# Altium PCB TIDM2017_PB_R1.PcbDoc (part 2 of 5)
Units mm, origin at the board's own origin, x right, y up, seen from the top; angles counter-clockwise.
Board outline 120 x 147.5 mm, 4 copper layers (Top Layer, L2, L3, Bottom Layer), stack 1.413 mm thick; 117 components, 53 nets, 3137 pads, 96 vias.
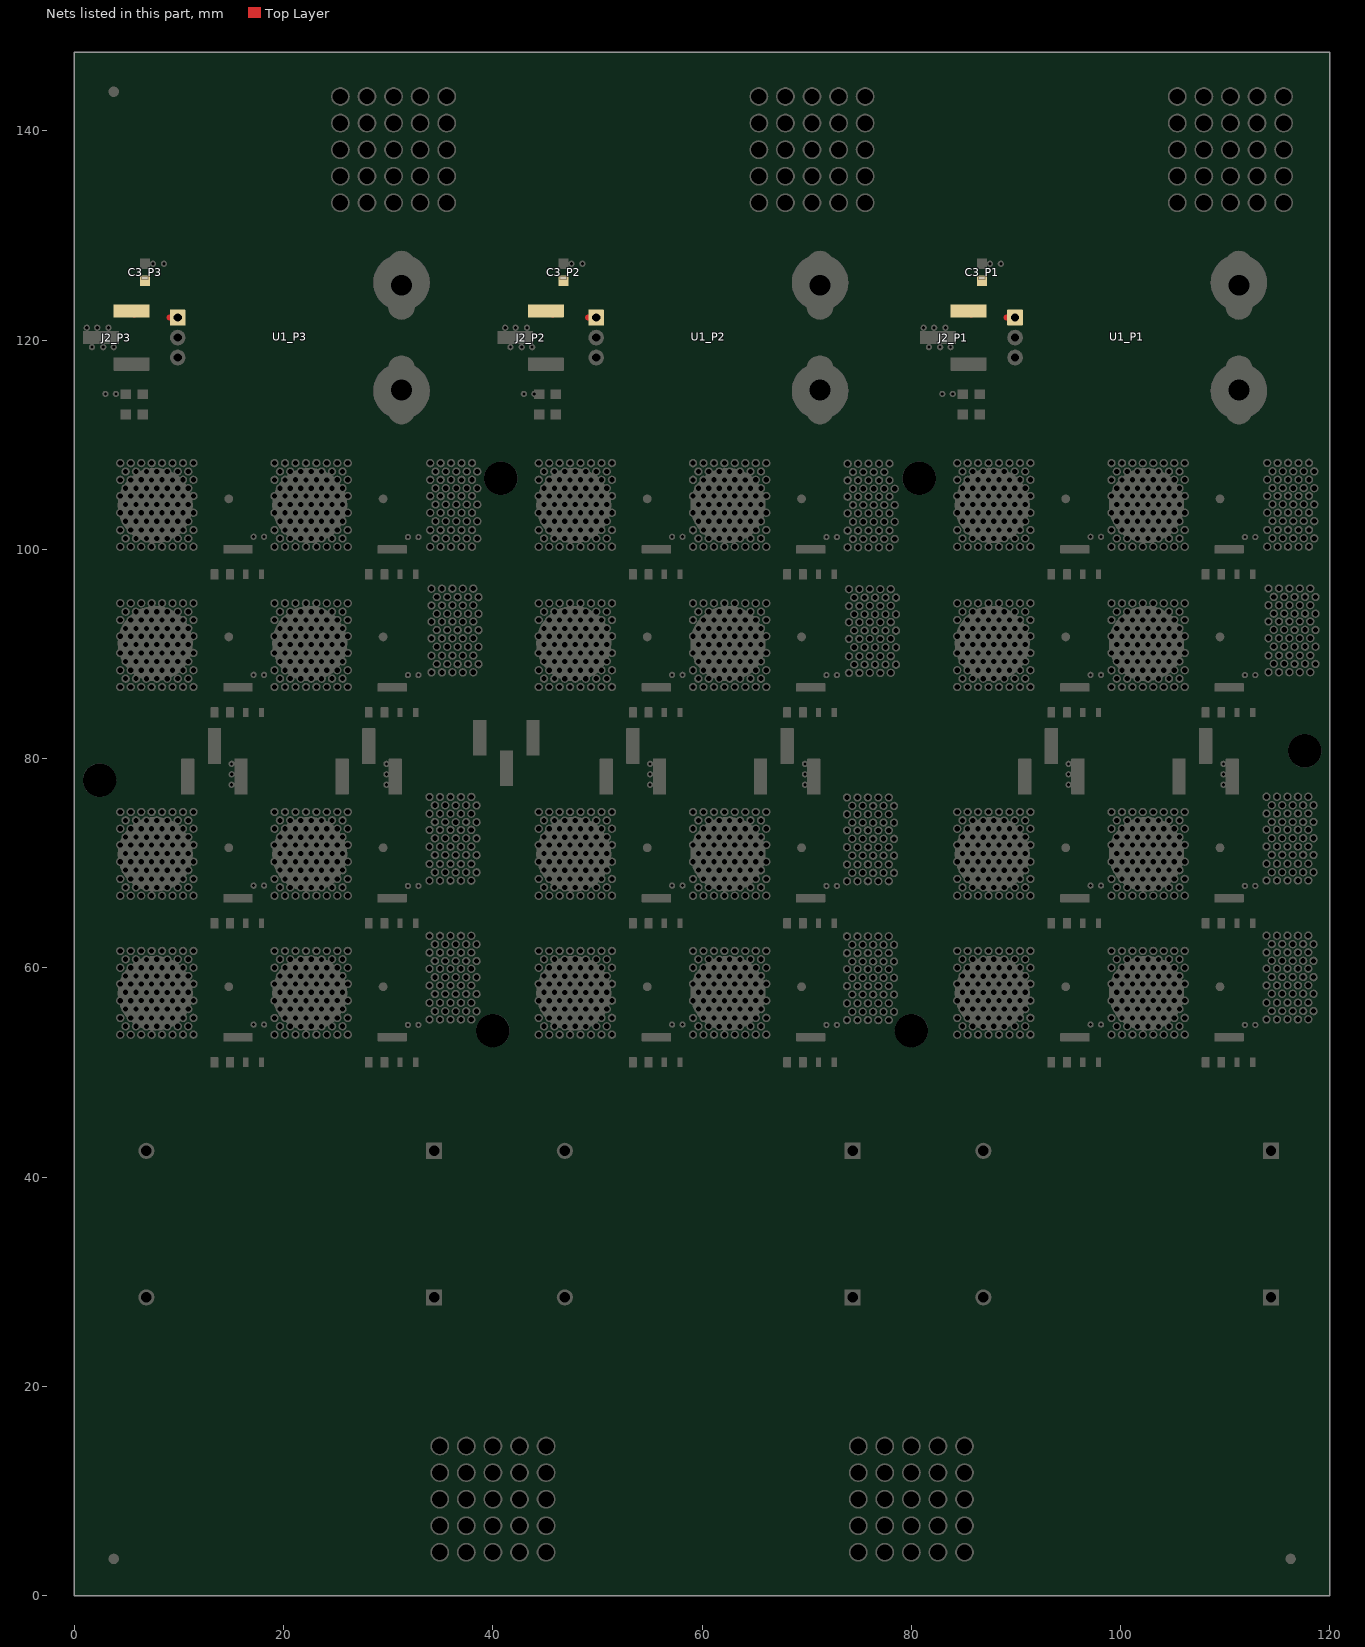
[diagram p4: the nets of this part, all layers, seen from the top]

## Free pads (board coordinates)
  round 0.6 hole 0.3: 2(1.175,121.183) 2(1.675,119.33) 2(2.175,121.186) 2(2.75,119.33) 2(2.955,114.858) 2(3.25,121.186) 2(3.75,119.33) 2(3.955,114.858) 2(7.5,127.3) 2(8.55,127.3) 2(15.026,77.5) 2(15.026,79.5) 2(15.029,78.5) 2(17.126,54.572) 2(17.126,67.855) 2(17.126,88.008) 2(17.126,101.203) 2(18.126,54.572) 2(18.126,67.855) 2(18.126,88.008) 2(18.126,101.203) 2(29.826,77.5) 2(29.826,78.5) 2(29.826,79.5) 2(31.876,54.547) 2(31.876,67.83) 2(31.876,87.983) 2(31.876,101.178) 2(32.876,54.547) 2(32.876,67.83) 2(32.876,87.983) 2(32.876,101.178) 2(41.175,121.183) 2(41.675,119.33) 2(42.175,121.186) 2(42.75,119.33) 2(42.955,114.858) 2(43.25,121.186) 2(43.75,119.33) 2(43.955,114.858) 2(47.5,127.3) 2(48.55,127.3) 2(55.026,77.5) 2(55.026,79.5) 2(55.029,78.5) 2(57.126,54.572) 2(57.126,67.855) 2(57.126,88.008) 2(57.126,101.203) 2(58.126,54.572) 2(58.126,67.855) 2(58.126,88.008) 2(58.126,101.203) 2(69.826,77.5) 2(69.826,78.5) 2(69.826,79.5) 2(71.876,54.547) 2(71.876,67.83) 2(71.876,87.983) 2(71.876,101.178) 2(72.876,54.547) 2(72.876,67.83) 2(72.876,87.983) 2(72.876,101.178) 2(81.175,121.183) 2(81.675,119.33) 2(82.175,121.186) 2(82.75,119.33) 2(82.955,114.858) 2(83.25,121.186) 2(83.75,119.33) 2(83.955,114.858) 2(87.5,127.3) 2(88.55,127.3) 2(95.026,77.5) 2(95.026,79.5) 2(95.029,78.5) 2(97.126,54.572) 2(97.126,67.855) 2(97.126,88.008) 2(97.126,101.203) 2(98.126,54.572) 2(98.126,67.855) 2(98.126,88.008) 2(98.126,101.203) 2(109.826,77.5) 2(109.826,78.5) 2(109.826,79.5) 2(111.876,54.547) 2(111.876,67.83) 2(111.876,87.983) 2(111.876,101.178) 2(112.876,54.547) 2(112.876,67.83) 2(112.876,87.983) 2(112.876,101.178)
  round 0.8 hole 0.5: 2(4.376,53.611) 2(4.376,55.211) 2(4.376,56.861) 2(4.376,58.461) 2(4.376,60.014) 2(4.376,61.614) 2(4.376,66.894) 2(4.376,68.494) 2(4.376,70.144) 2(4.376,71.744) 2(4.376,73.297) 2(4.376,74.897) 2(4.376,86.847) 2(4.376,88.447) 2(4.376,90.097) 2(4.376,91.697) 2(4.376,93.25) 2(4.376,94.85) 2(4.376,100.242) 2(4.376,101.842) 2(4.376,103.492) 2(4.376,105.092) 2(4.376,106.644) 2(4.376,108.244) 2(4.889,54.409) 2(4.889,56.059) 2(4.889,57.659) 2(4.889,59.212) 2(4.889,60.812) 2(4.889,67.693) 2(4.889,69.343) 2(4.889,70.943) 2(4.889,72.496) 2(4.889,74.096) 2(4.889,87.646) 2(4.889,89.296) 2(4.889,90.896) 2(4.889,92.448) 2(4.889,94.048) 2(4.889,101.04) 2(4.889,102.69) 2(4.889,104.29) 2(4.889,105.843) 2(4.889,107.443) 2(5.376,53.611) 2(5.376,55.211) 2(5.376,56.861) 2(5.376,58.461) 2(5.376,60.014) 2(5.376,61.614) 2(5.376,66.894) 2(5.376,68.494) 2(5.376,70.144) 2(5.376,71.744) 2(5.376,73.297) 2(5.376,74.897) 2(5.376,86.847) 2(5.376,88.447) 2(5.376,90.097) 2(5.376,91.697) 2(5.376,93.25) 2(5.376,94.85) 2(5.376,100.242) 2(5.376,101.842) 2(5.376,103.492) 2(5.376,105.092) 2(5.376,106.644) 2(5.376,108.244) 2(5.876,54.409) 2(5.876,56.059) 2(5.876,57.659) 2(5.876,59.212) 2(5.876,60.812) 2(5.876,67.693) 2(5.876,69.343) 2(5.876,70.943) 2(5.876,72.496) 2(5.876,74.096) 2(5.876,87.646) 2(5.876,89.296) 2(5.876,90.896) 2(5.876,92.448) 2(5.876,94.048) 2(5.876,101.04) 2(5.876,102.69) 2(5.876,104.29) 2(5.876,105.843) 2(5.876,107.443) 2(6.376,53.616) 2(6.376,55.216) 2(6.376,56.866) 2(6.376,58.466) 2(6.376,60.019) 2(6.376,61.619) 2(6.376,66.9) 2(6.376,68.5) 2(6.376,70.15) 2(6.376,71.75) 2(6.376,73.303) 2(6.376,74.903) 2(6.376,86.853) 2(6.376,88.453) 2(6.376,90.103) 2(6.376,91.703) 2(6.376,93.256) 2(6.376,94.855) 2(6.376,100.247) 2(6.376,101.847) 2(6.376,103.497) 2(6.376,105.097) 2(6.376,106.65) 2(6.376,108.25) 2(6.876,54.404) 2(6.876,56.054) 2(6.876,57.654) 2(6.876,59.207) 2(6.876,60.807) 2(6.876,67.687) 2(6.876,69.337) 2(6.876,70.937) 2(6.876,72.49) 2(6.876,74.09) 2(6.876,87.64) 2(6.876,89.29) 2(6.876,90.89) 2(6.876,92.443) 2(6.876,94.043) 2(6.876,101.035) 2(6.876,102.685) 2(6.876,104.285) 2(6.876,105.837) 2(6.876,107.437) 2(7.376,53.611) 2(7.376,55.211) 2(7.376,56.861) 2(7.376,58.461) 2(7.376,60.014) 2(7.376,61.614) 2(7.376,66.894) 2(7.376,68.494) 2(7.376,70.144) 2(7.376,71.744) 2(7.376,73.297) 2(7.376,74.897) 2(7.376,86.847) 2(7.376,88.447) 2(7.376,90.097) 2(7.376,91.697) 2(7.376,93.25) 2(7.376,94.85) 2(7.376,100.242) 2(7.376,101.842) 2(7.376,103.492) 2(7.376,105.092) 2(7.376,106.644) 2(7.376,108.244) 2(7.876,54.409) 2(7.876,56.059) 2(7.876,57.659) 2(7.876,59.212) 2(7.876,60.812) 2(7.876,67.693) 2(7.876,69.343) 2(7.876,70.943) 2(7.876,72.496) 2(7.876,74.096) 2(7.876,87.646) 2(7.876,89.296) 2(7.876,90.896) 2(7.876,92.448) 2(7.876,94.048) 2(7.876,101.04) 2(7.876,102.69) 2(7.876,104.29) 2(7.876,105.843) 2(7.876,107.443) 2(8.376,53.616) 2(8.376,55.216) 2(8.376,56.866) 2(8.376,58.466) 2(8.376,60.019) 2(8.376,61.619) 2(8.376,66.9) 2(8.376,68.5) 2(8.376,70.15) 2(8.376,71.75) 2(8.376,73.303) 2(8.376,74.903) 2(8.376,86.853) 2(8.376,88.453) 2(8.376,90.103) 2(8.376,91.703) 2(8.376,93.256) 2(8.376,94.855) 2(8.376,100.247) 2(8.376,101.847) 2(8.376,103.497) 2(8.376,105.097) 2(8.376,106.65) 2(8.376,108.25) 2(8.876,54.404) 2(8.876,56.054) 2(8.876,57.654) 2(8.876,59.207) 2(8.876,60.807) 2(8.876,67.687) 2(8.876,69.337) 2(8.876,70.937) 2(8.876,72.49) 2(8.876,74.09) 2(8.876,87.64) 2(8.876,89.29) 2(8.876,90.89) 2(8.876,92.443) 2(8.876,94.043) 2(8.876,101.035) 2(8.876,102.685) 2(8.876,104.285) 2(8.876,105.837) 2(8.876,107.437) 2(9.376,53.611) 2(9.376,55.211) 2(9.376,56.861) 2(9.376,58.461) 2(9.376,60.014) 2(9.376,61.614) 2(9.376,66.894) 2(9.376,68.494) 2(9.376,70.144) 2(9.376,71.744) 2(9.376,73.297) 2(9.376,74.897) 2(9.376,86.847) 2(9.376,88.447) 2(9.376,90.097) 2(9.376,91.697) 2(9.376,93.25) 2(9.376,94.85) 2(9.376,100.242) 2(9.376,101.842) 2(9.376,103.492) 2(9.376,105.092) 2(9.376,106.644) 2(9.376,108.244) 2(9.876,54.409) 2(9.876,56.059) 2(9.876,57.659) 2(9.876,59.212) 2(9.876,60.812) 2(9.876,67.693) 2(9.876,69.343) 2(9.876,70.943) 2(9.876,72.496) 2(9.876,74.096) 2(9.876,87.646) 2(9.876,89.296) 2(9.876,90.896) 2(9.876,92.448) 2(9.876,94.048) 2(9.876,101.04) 2(9.876,102.69) 2(9.876,104.29) 2(9.876,105.843) 2(9.876,107.443) 2(10.376,53.616) 2(10.376,55.216) 2(10.376,56.866) 2(10.376,58.466) 2(10.376,60.019) 2(10.376,61.619) 2(10.376,66.9) 2(10.376,68.5) 2(10.376,70.15) 2(10.376,71.75) 2(10.376,73.303) 2(10.376,74.903) 2(10.376,86.853) 2(10.376,88.453) 2(10.376,90.103) 2(10.376,91.703) 2(10.376,93.256) 2(10.376,94.855) 2(10.376,100.247) 2(10.376,101.847) 2(10.376,103.497) 2(10.376,105.097) 2(10.376,106.65) 2(10.376,108.25) 2(10.876,54.409) 2(10.876,56.059) 2(10.876,57.659) 2(10.876,59.212) 2(10.876,60.812) 2(10.876,67.693) 2(10.876,69.343) 2(10.876,70.943) 2(10.876,72.496) 2(10.876,74.096) 2(10.876,87.646) 2(10.876,89.296) 2(10.876,90.896) 2(10.876,92.448) 2(10.876,94.048) 2(10.876,101.04) 2(10.876,102.69) 2(10.876,104.29) 2(10.876,105.843) 2(10.876,107.443) 2(11.376,53.616) 2(11.376,55.216) 2(11.376,56.866) 2(11.376,58.466) 2(11.376,60.019) 2(11.376,61.619) 2(11.376,66.9) 2(11.376,68.5) 2(11.376,70.15) 2(11.376,71.75) 2(11.376,73.303) 2(11.376,74.903) 2(11.376,86.853) 2(11.376,88.453) 2(11.376,90.103) 2(11.376,91.703) 2(11.376,93.256) 2(11.376,94.855) 2(11.376,100.247) 2(11.376,101.847) 2(11.376,103.497) 2(11.376,105.097) 2(11.376,106.65) 2(11.376,108.25) 2(19.126,53.611) 2(19.126,55.211) 2(19.126,56.861) 2(19.126,58.461) 2(19.126,60.014) 2(19.126,61.614) 2(19.126,66.894) 2(19.126,68.494) 2(19.126,70.144) 2(19.126,71.744) 2(19.126,73.297) 2(19.126,74.897) 2(19.126,86.847) 2(19.126,88.447) 2(19.126,90.097) 2(19.126,91.697) 2(19.126,93.25) 2(19.126,94.85) 2(19.126,100.242) 2(19.126,101.842) 2(19.126,103.492) 2(19.126,105.092) 2(19.126,106.644) 2(19.126,108.244) 2(19.639,54.409) 2(19.639,56.059) 2(19.639,57.659) 2(19.639,59.212) 2(19.639,60.812) 2(19.639,67.693) 2(19.639,69.343) 2(19.639,70.943) 2(19.639,72.496) 2(19.639,74.096) 2(19.639,87.646) 2(19.639,89.296) 2(19.639,90.896) 2(19.639,92.448) 2(19.639,94.048) 2(19.639,101.04) 2(19.639,102.69) 2(19.639,104.29) 2(19.639,105.843) 2(19.639,107.443) 2(20.126,53.611) 2(20.126,55.211) 2(20.126,56.861) 2(20.126,58.461) 2(20.126,60.014) 2(20.126,61.614) 2(20.126,66.894) 2(20.126,68.494) 2(20.126,70.144) 2(20.126,71.744) 2(20.126,73.297) 2(20.126,74.897) 2(20.126,86.847) 2(20.126,88.447) 2(20.126,90.097) 2(20.126,91.697) 2(20.126,93.25) 2(20.126,94.85) 2(20.126,100.242) 2(20.126,101.842) 2(20.126,103.492) 2(20.126,105.092) 2(20.126,106.644) 2(20.126,108.244) 2(20.626,54.409) 2(20.626,56.059) 2(20.626,57.659) 2(20.626,59.212) 2(20.626,60.812) 2(20.626,67.693) 2(20.626,69.343) 2(20.626,70.943) 2(20.626,72.496) 2(20.626,74.096) 2(20.626,87.646) 2(20.626,89.296) 2(20.626,90.896) 2(20.626,92.448) 2(20.626,94.048) 2(20.626,101.04) 2(20.626,102.69) 2(20.626,104.29) 2(20.626,105.843) 2(20.626,107.443) 2(21.126,53.616) 2(21.126,55.216) 2(21.126,56.866) 2(21.126,58.466) 2(21.126,60.019) 2(21.126,61.619) 2(21.126,66.9) 2(21.126,68.5) 2(21.126,70.15) 2(21.126,71.75) 2(21.126,73.303) 2(21.126,74.903) 2(21.126,86.853) 2(21.126,88.453) 2(21.126,90.103) 2(21.126,91.703) 2(21.126,93.256) 2(21.126,94.855) 2(21.126,100.247) 2(21.126,101.847) 2(21.126,103.497) 2(21.126,105.097) 2(21.126,106.65) 2(21.126,108.25) 2(21.626,54.404) 2(21.626,56.054) 2(21.626,57.654) 2(21.626,59.207) 2(21.626,60.807) 2(21.626,67.687) 2(21.626,69.337) 2(21.626,70.937) 2(21.626,72.49) 2(21.626,74.09) 2(21.626,87.64) 2(21.626,89.29) 2(21.626,90.89) 2(21.626,92.443) 2(21.626,94.043) 2(21.626,101.035) 2(21.626,102.685) 2(21.626,104.285) 2(21.626,105.837) 2(21.626,107.437) 2(22.126,53.611) 2(22.126,55.211) 2(22.126,56.861) 2(22.126,58.461) 2(22.126,60.014) 2(22.126,61.614) 2(22.126,66.894) 2(22.126,68.494) 2(22.126,70.144) 2(22.126,71.744) 2(22.126,73.297) 2(22.126,74.897) 2(22.126,86.847) 2(22.126,88.447) 2(22.126,90.097) 2(22.126,91.697) 2(22.126,93.25) 2(22.126,94.85) 2(22.126,100.242) 2(22.126,101.842) 2(22.126,103.492) 2(22.126,105.092) 2(22.126,106.644) 2(22.126,108.244) 2(22.626,54.409) 2(22.626,56.059) 2(22.626,57.659) 2(22.626,59.212) 2(22.626,60.812) 2(22.626,67.693) 2(22.626,69.343) 2(22.626,70.943) 2(22.626,72.496) 2(22.626,74.096) 2(22.626,87.646) 2(22.626,89.296) 2(22.626,90.896) 2(22.626,92.448) 2(22.626,94.048) 2(22.626,101.04) 2(22.626,102.69) 2(22.626,104.29) 2(22.626,105.843) 2(22.626,107.443) 2(23.126,53.616) 2(23.126,55.216) 2(23.126,56.866) 2(23.126,58.466) 2(23.126,60.019) 2(23.126,61.619) 2(23.126,66.9) 2(23.126,68.5) 2(23.126,70.15) 2(23.126,71.75) 2(23.126,73.303) 2(23.126,74.903) 2(23.126,86.853) 2(23.126,88.453) 2(23.126,90.103) 2(23.126,91.703) 2(23.126,93.256) 2(23.126,94.855) 2(23.126,100.247) 2(23.126,101.847) 2(23.126,103.497) 2(23.126,105.097) 2(23.126,106.65) 2(23.126,108.25) 2(23.626,54.404) 2(23.626,56.054) 2(23.626,57.654) 2(23.626,59.207) 2(23.626,60.807) 2(23.626,67.687) 2(23.626,69.337) 2(23.626,70.937) 2(23.626,72.49) 2(23.626,74.09) 2(23.626,87.64) 2(23.626,89.29) 2(23.626,90.89) 2(23.626,92.443) 2(23.626,94.043) 2(23.626,101.035) 2(23.626,102.685) 2(23.626,104.285) 2(23.626,105.837) 2(23.626,107.437) 2(24.126,53.611) 2(24.126,55.211) 2(24.126,56.861) 2(24.126,58.461) 2(24.126,60.014) 2(24.126,61.614) 2(24.126,66.894) 2(24.126,68.494) 2(24.126,70.144) 2(24.126,71.744) 2(24.126,73.297) 2(24.126,74.897) 2(24.126,86.847) 2(24.126,88.447) 2(24.126,90.097) 2(24.126,91.697) 2(24.126,93.25) 2(24.126,94.85) 2(24.126,100.242) 2(24.126,101.842) 2(24.126,103.492) 2(24.126,105.092) 2(24.126,106.644) 2(24.126,108.244) 2(24.626,54.409) 2(24.626,56.059) 2(24.626,57.659) 2(24.626,59.212) 2(24.626,60.812) 2(24.626,67.693) 2(24.626,69.343) 2(24.626,70.943) 2(24.626,72.496) 2(24.626,74.096) 2(24.626,87.646) 2(24.626,89.296) 2(24.626,90.896) 2(24.626,92.448) 2(24.626,94.048) 2(24.626,101.04) 2(24.626,102.69) 2(24.626,104.29) 2(24.626,105.843) 2(24.626,107.443) 2(25.126,53.616) 2(25.126,55.216) 2(25.126,56.866) 2(25.126,58.466) 2(25.126,60.019) 2(25.126,61.619) 2(25.126,66.9) 2(25.126,68.5) 2(25.126,70.15) 2(25.126,71.75) 2(25.126,73.303) 2(25.126,74.903) 2(25.126,86.853) 2(25.126,88.453) 2(25.126,90.103) 2(25.126,91.703) 2(25.126,93.256) 2(25.126,94.855) 2(25.126,100.247) 2(25.126,101.847) 2(25.126,103.497) 2(25.126,105.097) 2(25.126,106.65) 2(25.126,108.25) 2(25.626,54.409) 2(25.626,56.059) 2(25.626,57.659) 2(25.626,59.212) 2(25.626,60.812) 2(25.626,67.693) 2(25.626,69.343) 2(25.626,70.943) 2(25.626,72.496) 2(25.626,74.096) 2(25.626,87.646) 2(25.626,89.296) 2(25.626,90.896) 2(25.626,92.448) 2(25.626,94.048) 2(25.626,101.04) 2(25.626,102.69) 2(25.626,104.29) 2(25.626,105.843) 2(25.626,107.443) 2(26.126,53.616) 2(26.126,55.216) 2(26.126,56.866) 2(26.126,58.466) 2(26.126,60.019) 2(26.126,61.619) 2(26.126,66.9) 2(26.126,68.5) 2(26.126,70.15) 2(26.126,71.75) 2(26.126,73.303) 2(26.126,74.903) 2(26.126,86.853) 2(26.126,88.453) 2(26.126,90.103) 2(26.126,91.703) 2(26.126,93.256) 2(26.126,94.855) 2(26.126,100.247) 2(26.126,101.847) 2(26.126,103.497) 2(26.126,105.097) 2(26.126,106.65) 2(26.126,108.25) 2(33.939,55.054) 2(33.939,56.654) 2(33.939,58.304) 2(33.939,59.904) 2(33.939,61.457) 2(33.939,63.057) 2(33.939,68.332) 2(33.939,69.932) 2(33.939,71.582) 2(33.939,73.182) 2(33.939,74.735) 2(33.939,76.335) 2(34.001,100.242) 2(34.001,101.842) 2(34.001,103.492) 2(34.001,105.092) 2(34.001,106.644) 2(34.001,108.244) 2(34.126,88.242) 2(34.126,89.842) 2(34.126,91.492) 2(34.126,93.092) 2(34.126,94.644) 2(34.126,96.244) 2(34.452,55.852) 2(34.452,57.502) 2(34.452,59.102) 2(34.452,60.655) 2(34.452,62.255) 2(34.452,69.13) 2(34.452,70.78) 2(34.452,72.38) 2(34.452,73.933) 2(34.452,75.533) 2(34.514,101.04) 2(34.514,102.69) 2(34.514,104.29) 2(34.514,105.843) 2(34.514,107.443) 2(34.639,89.04) 2(34.639,90.69) 2(34.639,92.29) 2(34.639,93.843) 2(34.639,95.443) 2(34.939,55.054) 2(34.939,56.654) 2(34.939,58.304) 2(34.939,59.904) 2(34.939,61.457) 2(34.939,63.057) 2(34.939,68.332) 2(34.939,69.932) 2(34.939,71.582) 2(34.939,73.182) 2(34.939,74.735) 2(34.939,76.335) 2(35.001,100.242) 2(35.001,101.842) 2(35.001,103.492) 2(35.001,105.092) 2(35.001,106.644) 2(35.001,108.244) 2(35.126,88.242) 2(35.126,89.842) 2(35.126,91.492) 2(35.126,93.092) 2(35.126,94.644) 2(35.126,96.244) 2(35.439,55.852) 2(35.439,57.502) 2(35.439,59.102) 2(35.439,60.655) 2(35.439,62.255) 2(35.439,69.13) 2(35.439,70.78) 2(35.439,72.38) 2(35.439,73.933) 2(35.439,75.533) 2(35.501,101.04) 2(35.501,102.69) 2(35.501,104.29) 2(35.501,105.843) 2(35.501,107.443) 2(35.626,89.04) 2(35.626,90.69) 2(35.626,92.29) 2(35.626,93.843) 2(35.626,95.443) 2(35.939,55.059) 2(35.939,56.659) 2(35.939,58.309) 2(35.939,59.909) 2(35.939,61.462) 2(35.939,63.062) 2(35.939,68.337) 2(35.939,69.937) 2(35.939,71.587) 2(35.939,73.187) 2(35.939,74.74) 2(35.939,76.34) 2(36.001,100.247) 2(36.001,101.847) 2(36.001,103.497) 2(36.001,105.097) 2(36.001,106.65) 2(36.001,108.25) 2(36.126,88.247) 2(36.126,89.847) 2(36.126,91.497) 2(36.126,93.097) 2(36.126,94.65) 2(36.126,96.25) 2(36.439,55.847) 2(36.439,57.497) 2(36.439,59.097) 2(36.439,60.649) 2(36.439,62.249) 2(36.439,69.125) 2(36.439,70.775) 2(36.439,72.375) 2(36.439,73.927) 2(36.439,75.527) 2(36.501,101.035) 2(36.501,102.685) 2(36.501,104.285) 2(36.501,105.837) 2(36.501,107.437) 2(36.626,89.035) 2(36.626,90.685) 2(36.626,92.285) 2(36.626,93.837) 2(36.626,95.437) 2(36.939,55.054) 2(36.939,56.654) 2(36.939,58.304) 2(36.939,59.904) 2(36.939,61.457) 2(36.939,63.057) 2(36.939,68.332) 2(36.939,69.932) 2(36.939,71.582) 2(36.939,73.182) 2(36.939,74.735) 2(36.939,76.335) 2(37.001,100.242) 2(37.001,101.842) 2(37.001,103.492) 2(37.001,105.092) 2(37.001,106.644) 2(37.001,108.244) 2(37.126,88.242) 2(37.126,89.842) 2(37.126,91.492) 2(37.126,93.092) 2(37.126,94.644) 2(37.126,96.244) 2(37.439,55.852) 2(37.439,57.502) 2(37.439,59.102) 2(37.439,60.655) 2(37.439,62.255) 2(37.439,69.13) 2(37.439,70.78) 2(37.439,72.38) 2(37.439,73.933) 2(37.439,75.533) 2(37.501,101.04) 2(37.501,102.69) 2(37.501,104.29) 2(37.501,105.843) 2(37.501,107.443) 2(37.626,89.04) 2(37.626,90.69) 2(37.626,92.29) 2(37.626,93.843) 2(37.626,95.443) 2(37.939,55.059) 2(37.939,56.659) 2(37.939,58.309) 2(37.939,59.909) 2(37.939,61.462) 2(37.939,63.062) 2(37.939,68.337) 2(37.939,69.937) 2(37.939,71.587) 2(37.939,73.187) 2(37.939,74.74) 2(37.939,76.34) 2(38.001,100.247) 2(38.001,101.847) 2(38.001,103.497) 2(38.001,105.097) 2(38.001,106.65) 2(38.001,108.25) 2(38.126,88.247) 2(38.126,89.847) 2(38.126,91.497) 2(38.126,93.097) 2(38.126,94.65) 2(38.126,96.25) 2(38.439,55.847) 2(38.439,57.497) 2(38.439,59.097) 2(38.439,60.649) 2(38.439,62.249) 2(38.439,69.125) 2(38.439,70.775) 2(38.439,72.375) 2(38.439,73.927) 2(38.439,75.527) 2(38.501,101.035) 2(38.501,102.685) 2(38.501,104.285) 2(38.501,105.837) 2(38.501,107.437) 2(38.626,89.035) 2(38.626,90.685) 2(38.626,92.285) 2(38.626,93.837) 2(38.626,95.437) 2(44.376,53.611) 2(44.376,55.211) 2(44.376,56.861) 2(44.376,58.461) 2(44.376,60.014) 2(44.376,61.614) 2(44.376,66.894) 2(44.376,68.494) 2(44.376,70.144) 2(44.376,71.744) 2(44.376,73.297) 2(44.376,74.897) 2(44.376,86.847) 2(44.376,88.447) 2(44.376,90.097) 2(44.376,91.697) 2(44.376,93.25) 2(44.376,94.85) 2(44.376,100.242) 2(44.376,101.842) 2(44.376,103.492) 2(44.376,105.092) 2(44.376,106.644) 2(44.376,108.244) 2(44.889,54.409) 2(44.889,56.059) 2(44.889,57.659) 2(44.889,59.212) 2(44.889,60.812) 2(44.889,67.693) 2(44.889,69.343) 2(44.889,70.943) 2(44.889,72.496) 2(44.889,74.096) 2(44.889,87.646) 2(44.889,89.296) 2(44.889,90.896) 2(44.889,92.448) 2(44.889,94.048) 2(44.889,101.04) 2(44.889,102.69) 2(44.889,104.29) 2(44.889,105.843) 2(44.889,107.443) 2(45.376,53.611) 2(45.376,55.211) 2(45.376,56.861) 2(45.376,58.461) 2(45.376,60.014) 2(45.376,61.614) 2(45.376,66.894) 2(45.376,68.494) 2(45.376,70.144) 2(45.376,71.744) 2(45.376,73.297) 2(45.376,74.897) 2(45.376,86.847) 2(45.376,88.447) 2(45.376,90.097) 2(45.376,91.697) 2(45.376,93.25) 2(45.376,94.85) 2(45.376,100.242) 2(45.376,101.842) 2(45.376,103.492) 2(45.376,105.092) 2(45.376,106.644) 2(45.376,108.244) 2(45.876,54.409) 2(45.876,56.059) 2(45.876,57.659) 2(45.876,59.212) 2(45.876,60.812) 2(45.876,67.693) 2(45.876,69.343) 2(45.876,70.943) 2(45.876,72.496) 2(45.876,74.096) 2(45.876,87.646) 2(45.876,89.296) 2(45.876,90.896) 2(45.876,92.448) 2(45.876,94.048) 2(45.876,101.04) 2(45.876,102.69) 2(45.876,104.29) 2(45.876,105.843) 2(45.876,107.443) 2(46.376,53.616) 2(46.376,55.216) 2(46.376,56.866) 2(46.376,58.466) 2(46.376,60.019) 2(46.376,61.619) 2(46.376,66.9) 2(46.376,68.5) 2(46.376,70.15) 2(46.376,71.75) 2(46.376,73.303) 2(46.376,74.903) 2(46.376,86.853) 2(46.376,88.453) 2(46.376,90.103) 2(46.376,91.703) 2(46.376,93.256) 2(46.376,94.855) 2(46.376,100.247) 2(46.376,101.847) 2(46.376,103.497) 2(46.376,105.097) 2(46.376,106.65) 2(46.376,108.25) 2(46.876,54.404) 2(46.876,56.054) 2(46.876,57.654) 2(46.876,59.207) 2(46.876,60.807) 2(46.876,67.687) 2(46.876,69.337) 2(46.876,70.937) 2(46.876,72.49) 2(46.876,74.09) 2(46.876,87.64) 2(46.876,89.29) 2(46.876,90.89) 2(46.876,92.443) 2(46.876,94.043) 2(46.876,101.035) 2(46.876,102.685) 2(46.876,104.285) 2(46.876,105.837) 2(46.876,107.437) 2(47.376,53.611) 2(47.376,55.211) 2(47.376,56.861) 2(47.376,58.461) 2(47.376,60.014) 2(47.376,61.614) 2(47.376,66.894) 2(47.376,68.494) 2(47.376,70.144) 2(47.376,71.744) 2(47.376,73.297) 2(47.376,74.897) 2(47.376,86.847) 2(47.376,88.447) 2(47.376,90.097) 2(47.376,91.697) 2(47.376,93.25) 2(47.376,94.85) 2(47.376,100.242) 2(47.376,101.842) 2(47.376,103.492) 2(47.376,105.092) 2(47.376,106.644) 2(47.376,108.244) 2(47.876,54.409) 2(47.876,56.059) 2(47.876,57.659) 2(47.876,59.212) 2(47.876,60.812) 2(47.876,67.693) 2(47.876,69.343) 2(47.876,70.943) 2(47.876,72.496) 2(47.876,74.096) 2(47.876,87.646) 2(47.876,89.296) 2(47.876,90.896) 2(47.876,92.448) 2(47.876,94.048) 2(47.876,101.04) 2(47.876,102.69) 2(47.876,104.29) 2(47.876,105.843) 2(47.876,107.443) 2(48.376,53.616) 2(48.376,55.216) 2(48.376,56.866) 2(48.376,58.466) 2(48.376,60.019) 2(48.376,61.619) 2(48.376,66.9) 2(48.376,68.5) 2(48.376,70.15) 2(48.376,71.75) 2(48.376,73.303) 2(48.376,74.903) 2(48.376,86.853) 2(48.376,88.453) 2(48.376,90.103) 2(48.376,91.703) 2(48.376,93.256) 2(48.376,94.855) 2(48.376,100.247) 2(48.376,101.847) 2(48.376,103.497) 2(48.376,105.097) 2(48.376,106.65) 2(48.376,108.25) 2(48.876,54.404) 2(48.876,56.054) 2(48.876,57.654) 2(48.876,59.207) 2(48.876,60.807) 2(48.876,67.687) 2(48.876,69.337) 2(48.876,70.937) 2(48.876,72.49) 2(48.876,74.09) 2(48.876,87.64) 2(48.876,89.29) 2(48.876,90.89) 2(48.876,92.443) 2(48.876,94.043) 2(48.876,101.035) 2(48.876,102.685) 2(48.876,104.285) 2(48.876,105.837) 2(48.876,107.437) 2(49.376,53.611) 2(49.376,55.211) 2(49.376,56.861) 2(49.376,58.461) 2(49.376,60.014) 2(49.376,61.614) 2(49.376,66.894) 2(49.376,68.494) 2(49.376,70.144) 2(49.376,71.744) 2(49.376,73.297) 2(49.376,74.897) 2(49.376,86.847) 2(49.376,88.447) 2(49.376,90.097) 2(49.376,91.697) 2(49.376,93.25) 2(49.376,94.85) 2(49.376,100.242) 2(49.376,101.842) 2(49.376,103.492) 2(49.376,105.092) 2(49.376,106.644) 2(49.376,108.244) 2(49.876,54.409) 2(49.876,56.059) 2(49.876,57.659) 2(49.876,59.212) 2(49.876,60.812) 2(49.876,67.693) 2(49.876,69.343) 2(49.876,70.943) 2(49.876,72.496) 2(49.876,74.096) 2(49.876,87.646) 2(49.876,89.296) 2(49.876,90.896) 2(49.876,92.448) 2(49.876,94.048) 2(49.876,101.04) 2(49.876,102.69) 2(49.876,104.29) 2(49.876,105.843) 2(49.876,107.443) 2(50.376,53.616) 2(50.376,55.216) 2(50.376,56.866) 2(50.376,58.466) 2(50.376,60.019) 2(50.376,61.619) 2(50.376,66.9) 2(50.376,68.5) 2(50.376,70.15) 2(50.376,71.75) 2(50.376,73.303) 2(50.376,74.903) 2(50.376,86.853) 2(50.376,88.453) 2(50.376,90.103) 2(50.376,91.703) 2(50.376,93.256) 2(50.376,94.855) 2(50.376,100.247) 2(50.376,101.847) 2(50.376,103.497) 2(50.376,105.097) 2(50.376,106.65) 2(50.376,108.25) 2(50.876,54.409) 2(50.876,56.059) 2(50.876,57.659) 2(50.876,59.212) 2(50.876,60.812) 2(50.876,67.693) 2(50.876,69.343) 2(50.876,70.943) 2(50.876,72.496) 2(50.876,74.096) 2(50.876,87.646) 2(50.876,89.296) 2(50.876,90.896) 2(50.876,92.448) 2(50.876,94.048) 2(50.876,101.04) 2(50.876,102.69) 2(50.876,104.29) 2(50.876,105.843) 2(50.876,107.443) 2(51.376,53.616) 2(51.376,55.216) 2(51.376,56.866) 2(51.376,58.466) 2(51.376,60.019) 2(51.376,61.619) 2(51.376,66.9) 2(51.376,68.5) 2(51.376,70.15) 2(51.376,71.75) 2(51.376,73.303) 2(51.376,74.903) 2(51.376,86.853) 2(51.376,88.453) 2(51.376,90.103) 2(51.376,91.703) 2(51.376,93.256) 2(51.376,94.855) 2(51.376,100.247) 2(51.376,101.847) 2(51.376,103.497) 2(51.376,105.097) 2(51.376,106.65) 2(51.376,108.25) 2(59.126,53.611) 2(59.126,55.211) 2(59.126,56.861) 2(59.126,58.461) 2(59.126,60.014) 2(59.126,61.614) 2(59.126,66.894) 2(59.126,68.494) 2(59.126,70.144) 2(59.126,71.744) 2(59.126,73.297) 2(59.126,74.897) 2(59.126,86.847) 2(59.126,88.447) 2(59.126,90.097) 2(59.126,91.697) 2(59.126,93.25) 2(59.126,94.85) 2(59.126,100.242) 2(59.126,101.842) 2(59.126,103.492) 2(59.126,105.092) 2(59.126,106.644) 2(59.126,108.244) 2(59.639,54.409) 2(59.639,56.059) 2(59.639,57.659) 2(59.639,59.212) 2(59.639,60.812) 2(59.639,67.693) 2(59.639,69.343) 2(59.639,70.943) 2(59.639,72.496) 2(59.639,74.096) 2(59.639,87.646) 2(59.639,89.296) 2(59.639,90.896) 2(59.639,92.448) 2(59.639,94.048) 2(59.639,101.04) 2(59.639,102.69) 2(59.639,104.29) 2(59.639,105.843) 2(59.639,107.443) 2(60.126,53.611) 2(60.126,55.211) 2(60.126,56.861) 2(60.126,58.461) 2(60.126,60.014) 2(60.126,61.614) 2(60.126,66.894) 2(60.126,68.494) 2(60.126,70.144) 2(60.126,71.744) 2(60.126,73.297) 2(60.126,74.897) 2(60.126,86.847) 2(60.126,88.447) 2(60.126,90.097) 2(60.126,91.697) 2(60.126,93.25) 2(60.126,94.85) 2(60.126,100.242) 2(60.126,101.842) 2(60.126,103.492) 2(60.126,105.092) 2(60.126,106.644) 2(60.126,108.244) 2(60.626,54.409) 2(60.626,56.059) 2(60.626,57.659) 2(60.626,59.212) 2(60.626,60.812) 2(60.626,67.693) 2(60.626,69.343) 2(60.626,70.943) 2(60.626,72.496) 2(60.626,74.096) 2(60.626,87.646) 2(60.626,89.296) 2(60.626,90.896) 2(60.626,92.448) 2(60.626,94.048) 2(60.626,101.04) 2(60.626,102.69) 2(60.626,104.29) 2(60.626,105.843) 2(60.626,107.443) 2(61.126,53.616) 2(61.126,55.216) 2(61.126,56.866) 2(61.126,58.466) 2(61.126,60.019) 2(61.126,61.619) 2(61.126,66.9) 2(61.126,68.5) 2(61.126,70.15) 2(61.126,71.75) 2(61.126,73.303) 2(61.126,74.903) 2(61.126,86.853) 2(61.126,88.453) 2(61.126,90.103) 2(61.126,91.703) 2(61.126,93.256) 2(61.126,94.855) 2(61.126,100.247) 2(61.126,101.847) 2(61.126,103.497) 2(61.126,105.097) 2(61.126,106.65) 2(61.126,108.25) 2(61.626,54.404) 2(61.626,56.054) 2(61.626,57.654) 2(61.626,59.207) 2(61.626,60.807) 2(61.626,67.687) 2(61.626,69.337) 2(61.626,70.937) 2(61.626,72.49) 2(61.626,74.09) 2(61.626,87.64) 2(61.626,89.29) 2(61.626,90.89) 2(61.626,92.443) 2(61.626,94.043) 2(61.626,101.035) 2(61.626,102.685) 2(61.626,104.285) 2(61.626,105.837) 2(61.626,107.437) 2(62.126,53.611) 2(62.126,55.211) 2(62.126,56.861) 2(62.126,58.461) 2(62.126,60.014) 2(62.126,61.614) 2(62.126,66.894) 2(62.126,68.494) 2(62.126,70.144) 2(62.126,71.744) 2(62.126,73.297) 2(62.126,74.897) 2(62.126,86.847) 2(62.126,88.447) 2(62.126,90.097) 2(62.126,91.697) 2(62.126,93.25) 2(62.126,94.85) 2(62.126,100.242) 2(62.126,101.842) 2(62.126,103.492) 2(62.126,105.092) 2(62.126,106.644) 2(62.126,108.244) 2(62.626,54.409) 2(62.626,56.059) 2(62.626,57.659) 2(62.626,59.212) 2(62.626,60.812) 2(62.626,67.693) 2(62.626,69.343) 2(62.626,70.943) 2(62.626,72.496) 2(62.626,74.096) 2(62.626,87.646) 2(62.626,89.296) 2(62.626,90.896) 2(62.626,92.448) 2(62.626,94.048) 2(62.626,101.04) 2(62.626,102.69) 2(62.626,104.29) 2(62.626,105.843) 2(62.626,107.443) 2(63.126,53.616) 2(63.126,55.216) 2(63.126,56.866) 2(63.126,58.466) 2(63.126,60.019) 2(63.126,61.619) 2(63.126,66.9) 2(63.126,68.5) 2(63.126,70.15) 2(63.126,71.75) 2(63.126,73.303) 2(63.126,74.903) 2(63.126,86.853) 2(63.126,88.453) 2(63.126,90.103) 2(63.126,91.703) 2(63.126,93.256) 2(63.126,94.855) 2(63.126,100.247) 2(63.126,101.847) 2(63.126,103.497) 2(63.126,105.097) 2(63.126,106.65) 2(63.126,108.25) 2(63.626,54.404) 2(63.626,56.054) 2(63.626,57.654) 2(63.626,59.207) 2(63.626,60.807) 2(63.626,67.687) 2(63.626,69.337) 2(63.626,70.937) 2(63.626,72.49) 2(63.626,74.09) 2(63.626,87.64) 2(63.626,89.29) 2(63.626,90.89) 2(63.626,92.443) 2(63.626,94.043) 2(63.626,101.035) 2(63.626,102.685) 2(63.626,104.285) 2(63.626,105.837) 2(63.626,107.437) 2(64.126,53.611) 2(64.126,55.211) 2(64.126,56.861) 2(64.126,58.461) 2(64.126,60.014) 2(64.126,61.614) 2(64.126,66.894) 2(64.126,68.494) 2(64.126,70.144) 2(64.126,71.744) 2(64.126,73.297) 2(64.126,74.897) 2(64.126,86.847) 2(64.126,88.447) 2(64.126,90.097) 2(64.126,91.697) 2(64.126,93.25) 2(64.126,94.85) 2(64.126,100.242) 2(64.126,101.842) 2(64.126,103.492) 2(64.126,105.092) 2(64.126,106.644) 2(64.126,108.244) 2(64.626,54.409) 2(64.626,56.059) 2(64.626,57.659) 2(64.626,59.212) 2(64.626,60.812) 2(64.626,67.693) 2(64.626,69.343) 2(64.626,70.943) 2(64.626,72.496) 2(64.626,74.096) 2(64.626,87.646) 2(64.626,89.296) 2(64.626,90.896) 2(64.626,92.448) 2(64.626,94.048) 2(64.626,101.04) 2(64.626,102.69) 2(64.626,104.29) 2(64.626,105.843) 2(64.626,107.443) 2(65.126,53.616) 2(65.126,55.216) 2(65.126,56.866) 2(65.126,58.466) 2(65.126,60.019) 2(65.126,61.619) 2(65.126,66.9) 2(65.126,68.5) 2(65.126,70.15) 2(65.126,71.75) 2(65.126,73.303) 2(65.126,74.903) 2(65.126,86.853) 2(65.126,88.453) 2(65.126,90.103) 2(65.126,91.703) 2(65.126,93.256) 2(65.126,94.855) 2(65.126,100.247) 2(65.126,101.847) 2(65.126,103.497) 2(65.126,105.097) 2(65.126,106.65) 2(65.126,108.25) 2(65.626,54.409) 2(65.626,56.059) 2(65.626,57.659) 2(65.626,59.212) 2(65.626,60.812) 2(65.626,67.693) 2(65.626,69.343) 2(65.626,70.943) 2(65.626,72.496) 2(65.626,74.096) 2(65.626,87.646) 2(65.626,89.296) 2(65.626,90.896) 2(65.626,92.448) 2(65.626,94.048) 2(65.626,101.04) 2(65.626,102.69) 2(65.626,104.29) 2(65.626,105.843) 2(65.626,107.443) 2(66.126,53.616) 2(66.126,55.216) 2(66.126,56.866) 2(66.126,58.466) 2(66.126,60.019) 2(66.126,61.619) 2(66.126,66.9) 2(66.126,68.5) 2(66.126,70.15) 2(66.126,71.75) 2(66.126,73.303) 2(66.126,74.903) 2(66.126,86.853) 2(66.126,88.453) 2(66.126,90.103) 2(66.126,91.703) 2(66.126,93.256) 2(66.126,94.855) 2(66.126,100.247) 2(66.126,101.847) 2(66.126,103.497) 2(66.126,105.097) 2(66.126,106.65) 2(66.126,108.25) 2(73.842,55.005) 2(73.842,56.605) 2(73.842,58.255) 2(73.842,59.855) 2(73.842,61.408) 2(73.842,63.008) 2(73.842,68.283) 2(73.842,69.883) 2(73.842,71.533) 2(73.842,73.133) 2(73.842,74.686) 2(73.842,76.286) 2(73.904,100.193) 2(73.904,101.793) 2(73.904,103.443) 2(73.904,105.043) 2(73.904,106.596) 2(73.904,108.196) 2(74.029,88.193) 2(74.029,89.793) 2(74.029,91.443) 2(74.029,93.043) 2(74.029,94.596) 2(74.029,96.196) 2(74.355,55.804) 2(74.355,57.454) 2(74.355,59.054) 2(74.355,60.606) 2(74.355,62.206) 2(74.355,69.082) 2(74.355,70.732) 2(74.355,72.332) 2(74.355,73.884) 2(74.355,75.484) 2(74.417,100.992) 2(74.417,102.642) 2(74.417,104.242) 2(74.417,105.794) 2(74.417,107.394) 2(74.542,88.992) 2(74.542,90.642) 2(74.542,92.242) 2(74.542,93.794) 2(74.542,95.394) 2(74.842,55.005) 2(74.842,56.605) 2(74.842,58.255) 2(74.842,59.855) 2(74.842,61.408) 2(74.842,63.008) 2(74.842,68.283) 2(74.842,69.883) 2(74.842,71.533) 2(74.842,73.133) 2(74.842,74.686) 2(74.842,76.286) 2(74.904,100.193) 2(74.904,101.793) 2(74.904,103.443) 2(74.904,105.043) 2(74.904,106.596) 2(74.904,108.196) 2(75.029,88.193) 2(75.029,89.793) 2(75.029,91.443) 2(75.029,93.043) 2(75.029,94.596) 2(75.029,96.196) 2(75.342,55.804) 2(75.342,57.454) 2(75.342,59.054) 2(75.342,60.606) 2(75.342,62.206) 2(75.342,69.082) 2(75.342,70.732) 2(75.342,72.332) 2(75.342,73.884) 2(75.342,75.484) 2(75.404,100.992) 2(75.404,102.642) 2(75.404,104.242) 2(75.404,105.794) 2(75.404,107.394) 2(75.529,88.992) 2(75.529,90.642) 2(75.529,92.242) 2(75.529,93.794) 2(75.529,95.394) 2(75.842,55.011) 2(75.842,56.611) 2(75.842,58.261) 2(75.842,59.861) 2(75.842,61.414) 2(75.842,63.014) 2(75.842,68.289) 2(75.842,69.889) 2(75.842,71.539) 2(75.842,73.139) 2(75.842,74.692) 2(75.842,76.292) 2(75.904,100.199) 2(75.904,101.799) 2(75.904,103.449) 2(75.904,105.049) 2(75.904,106.602) 2(75.904,108.202) 2(76.029,88.199) 2(76.029,89.799) 2(76.029,91.449) 2(76.029,93.049) 2(76.029,94.602) 2(76.029,96.202) 2(76.342,55.798) 2(76.342,57.448) 2(76.342,59.048) 2(76.342,60.601) 2(76.342,62.201) 2(76.342,69.076) 2(76.342,70.726) 2(76.342,72.326) 2(76.342,73.879) 2(76.342,75.479) 2(76.404,100.986) 2(76.404,102.636) 2(76.404,104.236) 2(76.404,105.789) 2(76.404,107.389) 2(76.529,88.986) 2(76.529,90.636) 2(76.529,92.236) 2(76.529,93.789) 2(76.529,95.389) 2(76.842,55.005) 2(76.842,56.605) 2(76.842,58.255) 2(76.842,59.855) 2(76.842,61.408) 2(76.842,63.008) 2(76.842,68.283) 2(76.842,69.883) 2(76.842,71.533) 2(76.842,73.133) 2(76.842,74.686) 2(76.842,76.286) 2(76.904,100.193) 2(76.904,101.793) 2(76.904,103.443) 2(76.904,105.043) 2(76.904,106.596) 2(76.904,108.196) 2(77.029,88.193) 2(77.029,89.793) 2(77.029,91.443) 2(77.029,93.043) 2(77.029,94.596) 2(77.029,96.196) 2(77.342,55.804) 2(77.342,57.454) 2(77.342,59.054) 2(77.342,60.606) 2(77.342,62.206) 2(77.342,69.082) 2(77.342,70.732) 2(77.342,72.332) 2(77.342,73.884) 2(77.342,75.484) 2(77.404,100.992) 2(77.404,102.642) 2(77.404,104.242) 2(77.404,105.794) 2(77.404,107.394) 2(77.529,88.992) 2(77.529,90.642) 2(77.529,92.242) 2(77.529,93.794) 2(77.529,95.394) 2(77.842,55.011) 2(77.842,56.611) 2(77.842,58.261) 2(77.842,59.861) 2(77.842,61.414) 2(77.842,63.014) 2(77.842,68.289) 2(77.842,69.889) 2(77.842,71.539) 2(77.842,73.139) 2(77.842,74.692) 2(77.842,76.292) 2(77.904,100.199) 2(77.904,101.799) 2(77.904,103.449) 2(77.904,105.049) 2(77.904,106.602) 2(77.904,108.202) 2(78.029,88.199) 2(78.029,89.799) 2(78.029,91.449) 2(78.029,93.049) 2(78.029,94.602) 2(78.029,96.202) 2(78.342,55.798) 2(78.342,57.448) 2(78.342,59.048) 2(78.342,60.601) 2(78.342,62.201) 2(78.342,69.076) 2(78.342,70.726) 2(78.342,72.326) 2(78.342,73.879) 2(78.342,75.479) 2(78.404,100.986) 2(78.404,102.636) 2(78.404,104.236) 2(78.404,105.789) 2(78.529,88.986) 2(78.529,90.636) 2(78.529,92.236) 2(78.529,93.789) 2(78.529,95.389) 2(84.376,53.611) 2(84.376,55.211) 2(84.376,56.861) 2(84.376,58.461) 2(84.376,60.014) 2(84.376,61.614) 2(84.376,66.894) 2(84.376,68.494) 2(84.376,70.144) 2(84.376,71.744) 2(84.376,73.297) 2(84.376,74.897) 2(84.376,86.847) 2(84.376,88.447) 2(84.376,90.097) 2(84.376,91.697) 2(84.376,93.25) 2(84.376,94.85) 2(84.376,100.242) 2(84.376,101.842) 2(84.376,103.492) 2(84.376,105.092) 2(84.376,106.644) 2(84.376,108.244) 2(84.889,54.409) 2(84.889,56.059) 2(84.889,57.659) 2(84.889,59.212) 2(84.889,60.812) 2(84.889,67.693) 2(84.889,69.343) 2(84.889,70.943) 2(84.889,72.496) 2(84.889,74.096) 2(84.889,87.646) 2(84.889,89.296) 2(84.889,90.896) 2(84.889,92.448) 2(84.889,94.048) 2(84.889,101.04) 2(84.889,102.69) 2(84.889,104.29) 2(84.889,105.843) 2(84.889,107.443) 2(85.376,53.611) 2(85.376,55.211) 2(85.376,56.861) 2(85.376,58.461) 2(85.376,60.014) 2(85.376,61.614) 2(85.376,66.894) 2(85.376,68.494) 2(85.376,70.144) 2(85.376,71.744) 2(85.376,73.297) 2(85.376,74.897) 2(85.376,86.847) 2(85.376,88.447) 2(85.376,90.097) 2(85.376,91.697) 2(85.376,93.25) 2(85.376,94.85) 2(85.376,100.242) 2(85.376,101.842) 2(85.376,103.492) 2(85.376,105.092) 2(85.376,106.644) 2(85.376,108.244) 2(85.876,54.409) 2(85.876,56.059) 2(85.876,57.659) 2(85.876,59.212) 2(85.876,60.812) 2(85.876,67.693) 2(85.876,69.343) 2(85.876,70.943) 2(85.876,72.496) 2(85.876,74.096) 2(85.876,87.646) 2(85.876,89.296) 2(85.876,90.896) 2(85.876,92.448) 2(85.876,94.048) 2(85.876,101.04) 2(85.876,102.69) 2(85.876,104.29) 2(85.876,105.843) 2(85.876,107.443) 2(86.376,53.616) 2(86.376,55.216) 2(86.376,56.866) 2(86.376,58.466) 2(86.376,60.019) 2(86.376,61.619) 2(86.376,66.9) 2(86.376,68.5) 2(86.376,70.15) 2(86.376,71.75) 2(86.376,73.303) 2(86.376,74.903) 2(86.376,86.853) 2(86.376,88.453) 2(86.376,90.103) 2(86.376,91.703) 2(86.376,93.256) 2(86.376,94.855) 2(86.376,100.247) 2(86.376,101.847) 2(86.376,103.497) 2(86.376,105.097) 2(86.376,106.65) 2(86.376,108.25) 2(86.876,54.404) 2(86.876,56.054) 2(86.876,57.654) 2(86.876,59.207) 2(86.876,60.807) 2(86.876,67.687) 2(86.876,69.337) 2(86.876,70.937) 2(86.876,72.49) 2(86.876,74.09) 2(86.876,87.64) 2(86.876,89.29) 2(86.876,90.89) 2(86.876,92.443) 2(86.876,94.043) 2(86.876,101.035) 2(86.876,102.685) 2(86.876,104.285) 2(86.876,105.837) 2(86.876,107.437) 2(87.376,53.611) 2(87.376,55.211) 2(87.376,56.861) 2(87.376,58.461) 2(87.376,60.014) 2(87.376,61.614) 2(87.376,66.894) 2(87.376,68.494) 2(87.376,70.144) 2(87.376,71.744) 2(87.376,73.297) 2(87.376,74.897) 2(87.376,86.847) 2(87.376,88.447) 2(87.376,90.097) 2(87.376,91.697) 2(87.376,93.25) 2(87.376,94.85) 2(87.376,100.242) 2(87.376,101.842) 2(87.376,103.492) 2(87.376,105.092) 2(87.376,106.644) 2(87.376,108.244) 2(87.876,54.409) 2(87.876,56.059) 2(87.876,57.659) 2(87.876,59.212) 2(87.876,60.812) 2(87.876,67.693) 2(87.876,69.343) 2(87.876,70.943) 2(87.876,72.496) 2(87.876,74.096) 2(87.876,87.646) 2(87.876,89.296) 2(87.876,90.896) 2(87.876,92.448) 2(87.876,94.048) 2(87.876,101.04) 2(87.876,102.69) 2(87.876,104.29) 2(87.876,105.843) 2(87.876,107.443) 2(88.376,53.616) 2(88.376,55.216) 2(88.376,56.866) 2(88.376,58.466) 2(88.376,60.019) 2(88.376,61.619) 2(88.376,66.9) 2(88.376,68.5) 2(88.376,70.15) 2(88.376,71.75) 2(88.376,73.303) 2(88.376,74.903) 2(88.376,86.853) 2(88.376,88.453) 2(88.376,90.103) 2(88.376,91.703) 2(88.376,93.256) 2(88.376,94.855) 2(88.376,100.247) 2(88.376,101.847) 2(88.376,103.497) 2(88.376,105.097) 2(88.376,106.65) 2(88.376,108.25) 2(88.876,54.404) 2(88.876,56.054) 2(88.876,57.654) 2(88.876,59.207) 2(88.876,60.807) 2(88.876,67.687) 2(88.876,69.337) 2(88.876,70.937) 2(88.876,72.49) 2(88.876,74.09) 2(88.876,87.64) 2(88.876,89.29) 2(88.876,90.89) 2(88.876,92.443) 2(88.876,94.043) 2(88.876,101.035) 2(88.876,102.685) 2(88.876,104.285) 2(88.876,105.837) 2(88.876,107.437) 2(89.376,53.611) 2(89.376,55.211) 2(89.376,56.861) 2(89.376,58.461) 2(89.376,60.014) 2(89.376,61.614) 2(89.376,66.894) 2(89.376,68.494) 2(89.376,70.144) 2(89.376,71.744) 2(89.376,73.297) 2(89.376,74.897) 2(89.376,86.847) 2(89.376,88.447) 2(89.376,90.097) 2(89.376,91.697) 2(89.376,93.25) 2(89.376,94.85) 2(89.376,100.242) 2(89.376,101.842) 2(89.376,103.492) 2(89.376,105.092) 2(89.376,106.644) 2(89.376,108.244) 2(89.876,54.409) 2(89.876,56.059) 2(89.876,57.659) 2(89.876,59.212) 2(89.876,60.812) 2(89.876,67.693) 2(89.876,69.343) 2(89.876,70.943) 2(89.876,72.496) 2(89.876,74.096) 2(89.876,87.646) 2(89.876,89.296) 2(89.876,90.896) 2(89.876,92.448) 2(89.876,94.048) 2(89.876,101.04) 2(89.876,102.69) 2(89.876,104.29) 2(89.876,105.843) 2(89.876,107.443) 2(90.376,53.616) 2(90.376,55.216) 2(90.376,56.866) 2(90.376,58.466) 2(90.376,60.019) 2(90.376,61.619) 2(90.376,66.9) 2(90.376,68.5) 2(90.376,70.15) 2(90.376,71.75) 2(90.376,73.303) 2(90.376,74.903) 2(90.376,86.853) 2(90.376,88.453) 2(90.376,90.103) 2(90.376,91.703) 2(90.376,93.256) 2(90.376,94.855) 2(90.376,100.247) 2(90.376,101.847) 2(90.376,103.497) 2(90.376,105.097) 2(90.376,106.65) 2(90.376,108.25) 2(90.876,54.409) 2(90.876,56.059) 2(90.876,57.659) 2(90.876,59.212) 2(90.876,60.812) 2(90.876,67.693) 2(90.876,69.343) 2(90.876,70.943) 2(90.876,72.496) 2(90.876,74.096) 2(90.876,87.646) 2(90.876,89.296) 2(90.876,90.896) 2(90.876,92.448) 2(90.876,94.048) 2(90.876,101.04) 2(90.876,102.69) 2(90.876,104.29) 2(90.876,105.843) 2(90.876,107.443) 2(91.376,53.616) 2(91.376,55.216) 2(91.376,56.866) 2(91.376,58.466) 2(91.376,60.019) 2(91.376,61.619) 2(91.376,66.9) 2(91.376,68.5) 2(91.376,70.15) 2(91.376,71.75) 2(91.376,73.303) 2(91.376,74.903) 2(91.376,86.853) 2(91.376,88.453) 2(91.376,90.103) 2(91.376,91.703) 2(91.376,93.256) 2(91.376,94.855) 2(91.376,100.247) 2(91.376,101.847) 2(91.376,103.497) 2(91.376,105.097) 2(91.376,106.65) 2(91.376,108.25) 2(99.126,53.611) 2(99.126,55.211) 2(99.126,56.861) 2(99.126,58.461) 2(99.126,60.014) 2(99.126,61.614) 2(99.126,66.894) 2(99.126,68.494) 2(99.126,70.144) 2(99.126,71.744) 2(99.126,73.297) 2(99.126,74.897) 2(99.126,86.847) 2(99.126,88.447) 2(99.126,90.097) 2(99.126,91.697) 2(99.126,93.25) 2(99.126,94.85) 2(99.126,100.242) 2(99.126,101.842) 2(99.126,103.492) 2(99.126,105.092) 2(99.126,106.644) 2(99.126,108.244) 2(99.639,54.409) 2(99.639,56.059) 2(99.639,57.659) 2(99.639,59.212) 2(99.639,60.812) 2(99.639,67.693) 2(99.639,69.343) 2(99.639,70.943) 2(99.639,72.496) 2(99.639,74.096) 2(99.639,87.646) 2(99.639,89.296) 2(99.639,90.896) 2(99.639,92.448) 2(99.639,94.048) 2(99.639,101.04) 2(99.639,102.69) 2(99.639,104.29) 2(99.639,105.843) 2(99.639,107.443) 2(100.126,53.611) 2(100.126,55.211) 2(100.126,56.861) 2(100.126,58.461) 2(100.126,60.014) 2(100.126,61.614) 2(100.126,66.894) 2(100.126,68.494) 2(100.126,70.144) 2(100.126,71.744) 2(100.126,73.297) 2(100.126,74.897) 2(100.126,86.847) 2(100.126,88.447) 2(100.126,90.097) 2(100.126,91.697) 2(100.126,93.25) 2(100.126,94.85) 2(100.126,100.242) 2(100.126,101.842) 2(100.126,103.492) 2(100.126,105.092) 2(100.126,106.644) 2(100.126,108.244) 2(100.626,54.409) 2(100.626,56.059) 2(100.626,57.659) 2(100.626,59.212) 2(100.626,60.812) 2(100.626,67.693) 2(100.626,69.343) 2(100.626,70.943) 2(100.626,72.496) 2(100.626,74.096) 2(100.626,87.646) 2(100.626,89.296) 2(100.626,90.896) 2(100.626,92.448) 2(100.626,94.048) 2(100.626,101.04) 2(100.626,102.69) 2(100.626,104.29) 2(100.626,105.843) 2(100.626,107.443) 2(101.126,53.616) 2(101.126,55.216) 2(101.126,56.866) 2(101.126,58.466) 2(101.126,60.019) 2(101.126,61.619) 2(101.126,66.9) 2(101.126,68.5) 2(101.126,70.15) 2(101.126,71.75) 2(101.126,73.303) 2(101.126,74.903) 2(101.126,86.853) 2(101.126,88.453) 2(101.126,90.103) 2(101.126,91.703) 2(101.126,93.256) 2(101.126,94.855) 2(101.126,100.247) 2(101.126,101.847) 2(101.126,103.497) 2(101.126,105.097) 2(101.126,106.65) 2(101.126,108.25) 2(101.626,54.404) 2(101.626,56.054) 2(101.626,57.654) 2(101.626,59.207) 2(101.626,60.807) 2(101.626,67.687) 2(101.626,69.337) 2(101.626,70.937) 2(101.626,72.49) 2(101.626,74.09) 2(101.626,87.64) 2(101.626,89.29) 2(101.626,90.89) 2(101.626,92.443) 2(101.626,94.043) 2(101.626,101.035) 2(101.626,102.685) 2(101.626,104.285) 2(101.626,105.837) 2(101.626,107.437) 2(102.126,53.611) 2(102.126,55.211) 2(102.126,56.861) 2(102.126,58.461) 2(102.126,60.014) 2(102.126,61.614) 2(102.126,66.894) 2(102.126,68.494) 2(102.126,70.144) 2(102.126,71.744) 2(102.126,73.297) 2(102.126,74.897) 2(102.126,86.847) 2(102.126,88.447) 2(102.126,90.097) 2(102.126,91.697) 2(102.126,93.25) 2(102.126,94.85) 2(102.126,100.242) 2(102.126,101.842) 2(102.126,103.492) 2(102.126,105.092) 2(102.126,106.644) 2(102.126,108.244) 2(102.626,54.409) 2(102.626,56.059) 2(102.626,57.659) 2(102.626,59.212) 2(102.626,60.812) 2(102.626,67.693) 2(102.626,69.343) 2(102.626,70.943) 2(102.626,72.496) 2(102.626,74.096) 2(102.626,87.646) 2(102.626,89.296) 2(102.626,90.896) 2(102.626,92.448) 2(102.626,94.048) 2(102.626,101.04) 2(102.626,102.69) 2(102.626,104.29) 2(102.626,105.843) 2(102.626,107.443) 2(103.126,53.616) 2(103.126,55.216) 2(103.126,56.866) 2(103.126,58.466) 2(103.126,60.019) 2(103.126,61.619) 2(103.126,66.9) 2(103.126,68.5) 2(103.126,70.15) 2(103.126,71.75) 2(103.126,73.303) 2(103.126,74.903) 2(103.126,86.853) 2(103.126,88.453) 2(103.126,90.103) 2(103.126,91.703) 2(103.126,93.256) 2(103.126,94.855) 2(103.126,100.247) 2(103.126,101.847) 2(103.126,103.497) 2(103.126,105.097) 2(103.126,106.65) 2(103.126,108.25) 2(103.626,54.404) 2(103.626,56.054) 2(103.626,57.654) 2(103.626,59.207) 2(103.626,60.807) 2(103.626,67.687) 2(103.626,69.337) 2(103.626,70.937) 2(103.626,72.49) 2(103.626,74.09) 2(103.626,87.64) 2(103.626,89.29) 2(103.626,90.89) 2(103.626,92.443) 2(103.626,94.043) 2(103.626,101.035) 2(103.626,102.685) 2(103.626,104.285) 2(103.626,105.837) 2(103.626,107.437) 2(104.126,53.611) 2(104.126,55.211) 2(104.126,56.861) 2(104.126,58.461) 2(104.126,60.014) 2(104.126,61.614) 2(104.126,66.894) 2(104.126,68.494) 2(104.126,70.144) 2(104.126,71.744) 2(104.126,73.297) 2(104.126,74.897) 2(104.126,86.847) 2(104.126,88.447) 2(104.126,90.097) 2(104.126,91.697) 2(104.126,93.25) 2(104.126,94.85) 2(104.126,100.242) 2(104.126,101.842) 2(104.126,103.492) 2(104.126,105.092) 2(104.126,106.644) 2(104.126,108.244) 2(104.626,54.409) 2(104.626,56.059) 2(104.626,57.659) 2(104.626,59.212) 2(104.626,60.812) 2(104.626,67.693) 2(104.626,69.343) 2(104.626,70.943) 2(104.626,72.496) 2(104.626,74.096) 2(104.626,87.646) 2(104.626,89.296) 2(104.626,90.896) 2(104.626,92.448) 2(104.626,94.048) 2(104.626,101.04) 2(104.626,102.69) 2(104.626,104.29) 2(104.626,105.843) 2(104.626,107.443) 2(105.126,53.616) 2(105.126,55.216) 2(105.126,56.866) 2(105.126,58.466) 2(105.126,60.019) 2(105.126,61.619) 2(105.126,66.9) 2(105.126,68.5) 2(105.126,70.15) 2(105.126,71.75) 2(105.126,73.303) 2(105.126,74.903) 2(105.126,86.853) 2(105.126,88.453) 2(105.126,90.103) 2(105.126,91.703) 2(105.126,93.256) 2(105.126,94.855) 2(105.126,100.247) 2(105.126,101.847) 2(105.126,103.497) 2(105.126,105.097) 2(105.126,106.65) 2(105.126,108.25) 2(105.626,54.409) 2(105.626,56.059) 2(105.626,57.659) 2(105.626,59.212) 2(105.626,60.812) 2(105.626,67.693) 2(105.626,69.343) 2(105.626,70.943) 2(105.626,72.496) 2(105.626,74.096) 2(105.626,87.646) 2(105.626,89.296) 2(105.626,90.896) 2(105.626,92.448) 2(105.626,94.048) 2(105.626,101.04) 2(105.626,102.69) 2(105.626,104.29) 2(105.626,105.843) 2(105.626,107.443) 2(106.126,53.616) 2(106.126,55.216) 2(106.126,56.866) 2(106.126,58.466) 2(106.126,60.019) 2(106.126,61.619) 2(106.126,66.9) 2(106.126,68.5) 2(106.126,70.15) 2(106.126,71.75) 2(106.126,73.303) 2(106.126,74.903) 2(106.126,86.853) 2(106.126,88.453) 2(106.126,90.103) 2(106.126,91.703) 2(106.126,93.256) 2(106.126,94.855) 2(106.126,100.247) 2(106.126,101.847) 2(106.126,103.497) 2(106.126,105.097) 2(106.126,106.65) 2(106.126,108.25) 2(113.944,55.071) 2(113.944,56.671) 2(113.944,58.321) 2(113.944,59.921) 2(113.944,61.474) 2(113.944,63.074) 2(113.944,68.349) 2(113.944,69.949) 2(113.944,71.599) 2(113.944,73.199) 2(113.944,74.752) 2(113.944,76.352) 2(114.006,100.259) 2(114.006,101.859) 2(114.006,103.509) 2(114.006,105.109) 2(114.006,106.661) 2(114.006,108.261) 2(114.131,88.259) 2(114.131,89.859) 2(114.131,91.509) 2(114.131,93.109) 2(114.131,94.661) 2(114.131,96.261) 2(114.457,55.869) 2(114.457,57.519) 2(114.457,59.119) 2(114.457,60.672) 2(114.457,62.272) 2(114.457,69.147) 2(114.457,70.797) 2(114.457,72.397) 2(114.457,73.95) 2(114.457,75.55) 2(114.519,101.057) 2(114.519,102.707) 2(114.519,104.307) 2(114.519,105.86) 2(114.519,107.46) 2(114.644,89.057) 2(114.644,90.707) 2(114.644,92.307) 2(114.644,93.86) 2(114.644,95.46) 2(114.944,55.071) 2(114.944,56.671) 2(114.944,58.321) 2(114.944,59.921) 2(114.944,61.474) 2(114.944,63.074) 2(114.944,68.349) 2(114.944,69.949) 2(114.944,71.599) 2(114.944,73.199) 2(114.944,74.752) 2(114.944,76.352) 2(115.006,100.259) 2(115.006,101.859) 2(115.006,103.509) 2(115.006,105.109) 2(115.006,106.661) 2(115.006,108.261) 2(115.131,88.259) 2(115.131,89.859) 2(115.131,91.509) 2(115.131,93.109) 2(115.131,94.661) 2(115.131,96.261) 2(115.444,55.869) 2(115.444,57.519) 2(115.444,59.119) 2(115.444,60.672) 2(115.444,62.272) 2(115.444,69.147) 2(115.444,70.797) 2(115.444,72.397) 2(115.444,73.95) 2(115.444,75.55) 2(115.506,101.057) 2(115.506,102.707) 2(115.506,104.307) 2(115.506,105.86) 2(115.506,107.46) 2(115.631,89.057) 2(115.631,90.707) 2(115.631,92.307) 2(115.631,93.86) 2(115.631,95.46) 2(115.944,55.076) 2(115.944,56.676) 2(115.944,58.326) 2(115.944,59.926) 2(115.944,61.479) 2(115.944,63.079) 2(115.944,68.354) 2(115.944,69.954) 2(115.944,71.604) 2(115.944,73.204) 2(115.944,74.757) 2(115.944,76.357) 2(116.006,100.264) 2(116.006,101.864) 2(116.006,103.514) 2(116.006,105.114) 2(116.006,106.667) 2(116.006,108.267) 2(116.131,88.264) 2(116.131,89.864) 2(116.131,91.514) 2(116.131,93.114) 2(116.131,94.667) 2(116.131,96.267) 2(116.444,55.864) 2(116.444,57.514) 2(116.444,59.114) 2(116.444,60.666) 2(116.444,62.266) 2(116.444,69.142) 2(116.444,70.792) 2(116.444,72.392) 2(116.444,73.944) 2(116.444,75.544) 2(116.506,101.052) 2(116.506,102.702) 2(116.506,104.302) 2(116.506,105.854) 2(116.506,107.454) 2(116.631,89.052) 2(116.631,90.702) 2(116.631,92.302) 2(116.631,93.854) 2(116.631,95.454) 2(116.944,55.071) 2(116.944,56.671) 2(116.944,58.321) 2(116.944,59.921) 2(116.944,61.474) 2(116.944,63.074) 2(116.944,68.349) 2(116.944,69.949) 2(116.944,71.599) 2(116.944,73.199) 2(116.944,74.752) 2(116.944,76.352) 2(117.006,100.259) 2(117.006,101.859) 2(117.006,103.509) 2(117.006,105.109) 2(117.006,106.661) 2(117.006,108.261) 2(117.131,88.259) 2(117.131,89.859) 2(117.131,91.509) 2(117.131,93.109) 2(117.131,94.661) 2(117.131,96.261) 2(117.444,55.869) 2(117.444,57.519) 2(117.444,59.119) 2(117.444,60.672) 2(117.444,62.272) 2(117.444,69.147) 2(117.444,70.797) 2(117.444,72.397) 2(117.444,73.95) 2(117.444,75.55) 2(117.506,101.057) 2(117.506,102.707) 2(117.506,104.307) 2(117.506,105.86) 2(117.506,107.46) 2(117.631,89.057) 2(117.631,90.707) 2(117.631,92.307) 2(117.631,93.86) 2(117.631,95.46) 2(117.944,55.076) 2(117.944,56.676) 2(117.944,58.326) 2(117.944,59.926) 2(117.944,61.479) 2(117.944,63.079) 2(117.944,68.354) 2(117.944,69.954) 2(117.944,71.604) 2(117.944,73.204) 2(117.944,74.757) 2(117.944,76.357) 2(118.006,100.264) 2(118.006,101.864) 2(118.006,103.514) 2(118.006,105.114) 2(118.006,106.667) 2(118.006,108.267) 2(118.131,88.264) 2(118.131,89.864) 2(118.131,91.514) 2(118.131,93.114) 2(118.131,94.667) 2(118.131,96.267) 2(118.444,55.864) 2(118.444,57.514) 2(118.444,59.114) 2(118.444,60.666) 2(118.444,62.266) 2(118.444,69.142) 2(118.444,70.792) 2(118.444,72.392) 2(118.444,73.944) 2(118.444,75.544) 2(118.506,101.052) 2(118.506,102.702) 2(118.506,104.302) 2(118.506,105.854) 2(118.506,107.454) 2(118.631,89.052) 2(118.631,90.702) 2(118.631,92.302) 2(118.631,93.854) 2(118.631,95.454)
  round 3.2 hole 3.2 unplated: 3(2.4,77.941) 3(40,54) 3(40.75,106.8) 3(80,54) 3(80.75,106.8) 3(117.6,80.75)

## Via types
v1: diameter 0.8, hole 0.5, Top Layer to Bottom Layer, 96 vias

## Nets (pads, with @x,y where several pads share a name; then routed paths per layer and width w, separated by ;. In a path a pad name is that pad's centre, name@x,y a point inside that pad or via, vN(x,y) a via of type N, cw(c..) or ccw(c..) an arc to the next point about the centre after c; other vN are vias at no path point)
+5V_P1: C3_P1.1 J2_P1.1 U1_P1.1 | length 0.4
  Top Layer w0.75: J2_P1.1@85.46,122.79 J2_P1.1@85.72,122.53
+5V_P2: C3_P2.1 J2_P2.1 U1_P2.1 | length 0.4
  Top Layer w0.75: J2_P2.1@45.46,122.79 J2_P2.1@45.72,122.53
+5V_P3: C3_P3.1 J2_P3.1 U1_P3.1 | length 0.4
  Top Layer w0.75: J2_P3.1@5.46,122.79 J2_P3.1@5.72,122.53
